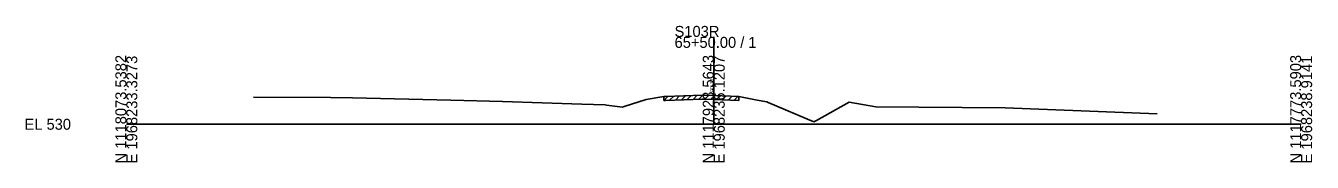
# Model space of a CAD drawing. Extents: x 974 to 1303, y 990 to 10019.
# Drawn here: x 974.3 to 1302.8, y 7990.3 to 8025.1 of the extents above; entities that cross this region are included whole.
import ezdxf

# ---------------------------------------------------------------- set-up
doc = ezdxf.new("R2010")
doc.units = 0
for name, color, linetype in [('Level 10', 7, 'Continuous'), ('Level 60', 7, 'Continuous'), ('Level 61', 7, 'Continuous'), ('Level 63', 7, 'Continuous')]:
    doc.layers.add(name, color=color, linetype=linetype)

msp = doc.modelspace()

# ---------------------------------------------------------------- linework, layer by layer
at = {"layer": 'Level 60'}
for p, q in [((1032.48, 8006.88), (1052.11, 8006.79)), ((1052.11, 8006.79), (1057.74, 8006.74)), ((1057.74, 8006.74), (1082.9, 8006.17)), ((1132.74, 8006.31), (1137.23, 8007.05)), ((1137.23, 8007.05), (1137.69, 8007.07)), ((1137.69, 8007.07), (1147.05, 8007.43)), ((1147.05, 8007.43), (1147.62, 8007.41)), ((1147.62, 8007.41), (1150, 8007.33)), ((1150, 8007.33), (1156.39, 8007.1)), ((1156.39, 8007.1), (1161.11, 8006.16)), ((1082.9, 8006.17), (1096.08, 8005.81)), ((1096.08, 8005.81), (1116.29, 8005.14)), ((1116.29, 8005.14), (1122.24, 8004.94)), ((1122.24, 8004.94), (1122.62, 8004.87)), ((1122.62, 8004.87), (1126.66, 8004.33)), ((1126.66, 8004.33), (1127.09, 8004.5)), ((1127.09, 8004.5), (1132.74, 8006.31)), ((1161.11, 8006.16), (1163.55, 8005.68)), ((1163.55, 8005.68), (1163.87, 8005.55)), ((1163.87, 8005.55), (1175.58, 8000.62)), ((1176.27, 8000.99), (1184.56, 8005.6)), ((1184.56, 8005.6), (1191.37, 8004.43)), ((1191.37, 8004.43), (1224.38, 8004.2)), ((1224.38, 8004.2), (1263.23, 8002.63)), ((1175.58, 8000.62), (1176.27, 8000.99))]:
    msp.add_line(p, q, dxfattribs=at)
at = {"layer": 'Level 61'}
for p, q in [((1137.23, 8006.05), (1138.27, 8007.09)), ((1137.23, 8006.05), (1137.23, 8007.05)), ((1137.69, 8006.07), (1147.05, 8006.43)), ((1138.73, 8006.11), (1139.77, 8007.15)), ((1140.23, 8006.16), (1141.27, 8007.21)), ((1141.73, 8006.22), (1142.77, 8007.26)), ((1143.23, 8006.28), (1144.27, 8007.32)), ((1144.73, 8006.34), (1145.77, 8007.38)), ((1146.23, 8006.4), (1147.25, 8007.42)), ((1147.05, 8006.43), (1147.62, 8006.41)), ((1147.62, 8006.41), (1150, 8006.33)), ((1147.73, 8006.4), (1148.69, 8007.37)), ((1149.23, 8006.35), (1150.19, 8007.32)), ((1150.73, 8006.3), (1151.69, 8007.27)), ((1152.23, 8006.25), (1153.19, 8007.21)), ((1153.73, 8006.2), (1154.69, 8007.16)), ((1155.23, 8006.14), (1156.19, 8007.11)), ((1156.39, 8007.1), (1156.39, 8006.1)), ((1137.23, 8006.05), (1137.69, 8006.07)), ((1150, 8006.33), (1156.39, 8006.1)), ((1156.39, 8006.1), (1156.39, 8006.1))]:
    msp.add_line(p, q, dxfattribs=at)
at = {"layer": 'Level 63'}
for p, q in [((1150, 8000), (1150, 8022.29)), ((1000, 8000), (1150, 8000)), ((1150, 8000), (1300, 8000))]:
    msp.add_line(p, q, dxfattribs=at)

# ---------------------------------------------------------------- texts
at = {"layer": 'Level 10'}
msp.add_text('537.33', height=0.9, rotation=90, dxfattribs=at).set_placement((1149.95, 8007.83))
at = {"layer": 'Level 63'}
for s, p in [('S103R', (1140, 8022.29)), ('65+50.00 / 1', (1140, 8019.49)), ('EL 530', (974, 7998.6))]:
    msp.add_text(s, height=2.8, dxfattribs=at).set_placement(p)
for s, p in [('N 1118073.5382', (1000, 7990)), ('E 1968233.3273', (1002.8, 7990)), ('N 1117923.5643', (1150, 7990)), ('E 1968236.1207', (1152.8, 7990)), ('N 1117773.5903', (1300, 7990)), ('E 1968238.9141', (1302.8, 7990))]:
    msp.add_text(s, height=2.8, rotation=90, dxfattribs=at).set_placement(p)

doc.saveas('drawing.dxf')
